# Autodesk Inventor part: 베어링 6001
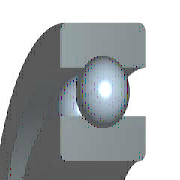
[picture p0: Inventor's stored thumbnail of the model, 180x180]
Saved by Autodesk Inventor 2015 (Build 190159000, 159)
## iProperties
IsCustomPart: 0
Created: 2015-10
Part Number: 베어링 6001
Material: 강철, 연강
Description: 깊은 그루브 볼 베어링
Document SubType Name: Modeling
Standard: KS B 2023
Designer: mdu
Standards Organization: KS
Language: ko-KR
Size Designation: 6001 - 12 x 28 x 8
Categories: <MemberInstance><Categories><Category DisplayName="샤프트 부품" InternalName="7f7aeb1f-a693-4053-b835-cee3144e0d98" Mnemonic="SHFT"><Category DisplayName="베어링" Inter
Density: 7.86 g/cm^3
Mass: 21.4855 g
Surface Area: 31.1809 cm^2
Volume: 2.73352 cm^3
Appearance: 강철
Author: mdu
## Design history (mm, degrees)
sketch "스케치" dims "d0" = 4.16 (= -0.26 x WD + 0.26 x BD)
  geometry: L1 (1.92, 10)-(6.08, 10); L2 (4, 10)-(4, 7.92); L3 (4, 10)-(4, 12.08); L4 (2.454, 8.608)-(0, 8.608); L5 (0, 6)-(8, 6); L6 (2.454, 11.392)-(0, 11.392); L7 (0, 14)-(8, 14); L8 (8, 6)-(8, 8.608); L9 (5.546, 8.608)-(8, 8.608); L10 (5.546, 11.392)-(8, 11.392); L11 (8, 14)-(8, 11.392); L12 (-1.4, 0)-(8.4, 0) reference; L13 (0, -0.3)-(0, 5.3) reference
  constraints: 22 end point, 4 point on line, 2 collinear, 2 perpendicular, 2 symmetric about line, 1 midpoint, 1 parallel, 14 other
  dimensions: "d9" = 12 diameter of L5 L12 (= WD); "d11" = 28 diameter of L7 L12 (= BD); "d12" = 8 distance between parallel lines of L8 L13 (= KB); "d13" = 17.216 diameter of L9 L12 (= 0.326 x BD + 0.674 x WD)
revolve "본체" stored, may be unused: angle "d6" = 90 deg
revolve "볼" stored, may be unused: angle "d7" = 90 deg
pattern_circular "IDS_ARRAYBALL[SIMPL:T]" dims angle "d3" = 360 deg
body "Solid1"
fillet "모깎기1" dims "d1" = 0.3 (= KRS)
other parameters: "WD" = 12 [user parameter; used in 5 equation terms], "BD" = 28 [user parameter; used in 5 equation terms], "KB" = 8 [user parameter; used in 1 equation term], "KRS" = 0.3 [user parameter; used in 1 equation term], "d4" = 0, "d5" = 0, "d8" = 0, "d14" = 0, "d15" = 0, "BBA" = 0 [user parameter], "BC0" = 2360000 [user parameter], "BC" = 5070000 [user parameter], "BR" = 14 (= 0.5 x BD) [user parameter], "WR" = 6 (= 0.5 x WD) [user parameter]
